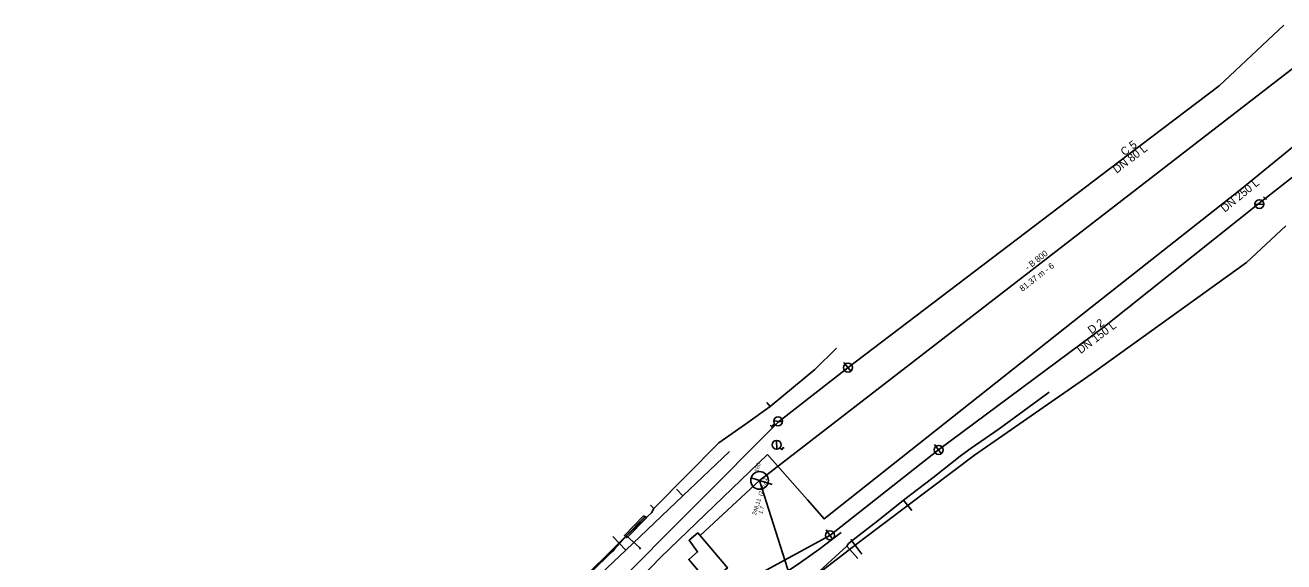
# Model space of a CAD drawing. Extents: x -600636 to -600148, y -1203980 to -1203569.
# Drawn here: x -600456.1 to -600313.9, y -1203630.1 to -1203569.5 of the extents above; entities that cross this region are included whole.
import ezdxf

# ---------------------------------------------------------------- set-up
doc = ezdxf.new("R2010")
doc.units = 0
for name, color, linetype in [('Cetin zam průběh', 7, 'Continuous'), ('EON podzemní NN', 7, 'Continuous'), ('GasNet NTL', 7, 'Continuous'), ('Implicitní', 7, 'Continuous'), ('VaK Břeclav_kanalizace', 7, 'Continuous'), ('Vak Břeclav_vodovod', 7, 'Continuous')]:
    doc.layers.add(name, color=color, linetype=linetype)

# ---------------------------------------------------------------- blocks, each defined once
blk = doc.blocks.new('MoSymbol 2')
at = {"layer": 'Implicitní'}
blk.add_line((0, 0.0005), (0, -0.00075), dxfattribs=at)
blk.add_circle((0, 0), 0.0005, dxfattribs=at)
blk = doc.blocks.new('MoSymbol 3')
at = {"layer": 'Implicitní'}
for p, q in [((-0.000365, -0.000365), (0.000365, 0.000365)), ((-0.000225, 0.00095), (0.000225, 0.00095)), ((0, 0.00095), (0, 0.0005))]:
    blk.add_line(p, q, dxfattribs=at)
blk.add_circle((0, 0), 0.0005, dxfattribs=at)
blk = doc.blocks.new('MoSymbol 4')
at = {"layer": 'Implicitní'}
for p, q in [((-0.000365, -0.000365), (0.000365, 0.000365)), ((0.0003, -0.0008), (0.0002, -0.00085))]:
    blk.add_line(p, q, dxfattribs=at)
blk.add_lwpolyline([(0, -0.0005), (0, -0.0008), (0.0003, -0.0008), (0.0002, -0.00075)], dxfattribs=at)
blk.add_circle((0, 0), 0.0005, dxfattribs=at)

msp = doc.modelspace()

# ---------------------------------------------------------------- linework, layer by layer
at = {"layer": 'Cetin zam průběh'}
for points in [[(-600403.75, -1203662.4), (-600400.59, -1203659.29), (-600391.04, -1203649.83), (-600378.25, -1203637.79), (-600376.97, -1203637.47), (-600375.66, -1203637.95), (-600375.36, -1203637.74), (-600369.01, -1203633.38), (-600361.52, -1203627.61), (-600348.82, -1203618.06), (-600335.53, -1203608.82), (-600318.11, -1203596.27), (-600313.64, -1203592.14)], [(-600371.93, -1203612.56), (-600366.88, -1203608.36), (-600364.43, -1203605.96)], [(-600356.85, -1203623.13), (-600353.54, -1203620.63), (-600350.46, -1203618.17), (-600349.88, -1203617.76), (-600349.23, -1203617.28), (-600346.05, -1203615.09), (-600340.39, -1203610.92)], [(-600385.06, -1203624.09), (-600377.73, -1203616.65), (-600374.7, -1203614.56), (-600371.93, -1203612.56)], [(-600371.93, -1203612.56), (-600372.32, -1203612.09)], [(-600377.73, -1203616.65), (-600374.7, -1203614.56)], [(-600353.54, -1203620.63), (-600350.46, -1203618.17)], [(-600388.16, -1203627.18), (-600385.34, -1203624.55), (-600385.06, -1203624.09)], [(-600385.06, -1203624.09), (-600385.47, -1203623.7)], [(-600359.74, -1203625.45), (-600356.85, -1203623.13)], [(-600356.85, -1203623.13), (-600355.91, -1203624.31)], [(-600388.16, -1203627.18), (-600385.34, -1203624.55)], [(-600363.25, -1203628.32), (-600363.07, -1203628.05), (-600361.87, -1203627.08), (-600359.74, -1203625.45)], [(-600389.61, -1203628.78), (-600389.52, -1203628.69), (-600388.16, -1203627.18)], [(-600389.52, -1203628.69), (-600388.16, -1203627.18)], [(-600388.16, -1203627.18), (-600386.71, -1203628.5)], [(-600388.16, -1203627.18), (-600386.71, -1203628.5), (-600386.58, -1203628.67)], [(-600368.09, -1203632.74), (-600363.25, -1203628.32)], [(-600363.25, -1203628.32), (-600362.03, -1203629.72)], [(-600363.07, -1203628.05), (-600361.87, -1203627.08)], [(-600396.73, -1203635.32), (-600394.24, -1203633.29), (-600389.88, -1203629.05)], [(-600389.88, -1203629.05), (-600389.61, -1203628.78)]]:
    msp.add_lwpolyline(points, dxfattribs=at)
at = {"layer": 'EON podzemní NN'}
msp.add_lwpolyline([(-600394.24, -1203633.14), (-600388.26, -1203627.25), (-600386.06, -1203624.99)], dxfattribs=at)
msp.add_lwpolyline([(-600386.23, -1203624.89), (-600385.88, -1203625.09), (-600388.12, -1203627.38), (-600388.4, -1203627.11)], close=True, dxfattribs=at)
at = {"layer": 'GasNet NTL'}
for points in [[(-600376.52, -1203617.62), (-600381.81, -1203622.65), (-600388.25, -1203628.77), (-600399.65, -1203639.6), (-600410.04, -1203649.48), (-600410.35, -1203649.77), (-600417.47, -1203657.21), (-600420.27, -1203660.14), (-600432.74, -1203673.17), (-600439.94, -1203680.7), (-600445.87, -1203686.85), (-600458.57, -1203700.01), (-600466.75, -1203707.26), (-600469.55, -1203709.74), (-600472.59, -1203712.26), (-600475.67, -1203714.29), (-600481.14, -1203718.36), (-600486.68, -1203722.48)], [(-600382.53, -1203621.89), (-600381.81, -1203622.65)], [(-600363.91, -1203626.79), (-600366.43, -1203628.72), (-600368.49, -1203630.18), (-600377.69, -1203636.35), (-600377.83, -1203636.45), (-600379.12, -1203637.4), (-600390.52, -1203649.08), (-600393.75, -1203652.39), (-600407.12, -1203666.06), (-600410.69, -1203669.71), (-600416.55, -1203675.06), (-600425.93, -1203683.63), (-600443.22, -1203700.03), (-600443.4, -1203700.21), (-600447.92, -1203704.5), (-600448.05, -1203704.62)], [(-600389.69, -1203627.25), (-600388.25, -1203628.77)], [(-600362.82, -1203627.58), (-600361.57, -1203629.22)]]:
    msp.add_lwpolyline(points, dxfattribs=at)
at = {"layer": 'VaK Břeclav_kanalizace'}
for p, q in [((-600309.64, -1203571.84), (-600373.13, -1203620.91)), ((-600373.13, -1203620.91), (-600379.85, -1203627.13)), ((-600373.13, -1203620.91), (-600367.91, -1203637.36))]:
    msp.add_line(p, q, dxfattribs=at)
msp.add_lwpolyline([(-600380.11, -1203626.82), (-600381.1, -1203627.66), (-600380.13, -1203628.99), (-600381.12, -1203629.83), (-600378.83, -1203632.54), (-600376.75, -1203630.79)], close=True, dxfattribs=at)
at = {"layer": 'Vak Břeclav_vodovod'}
for p, q in [((-600316.71, -1203589.64), (-600300.57, -1203576.9)), ((-600363.13, -1203608.16), (-600370.99, -1203614.29)), ((-600370.99, -1203614.29), (-600423.62, -1203667.02)), ((-600365.17, -1203627.11), (-600352.89, -1203617.46)), ((-600377.98, -1203634.08), (-600365.17, -1203627.11))]:
    msp.add_line(p, q, dxfattribs=at)
for points in [[(-600313.89, -1203569.48), (-600321.18, -1203576.33), (-600332.51, -1203584.93), (-600363.13, -1203608.16)], [(-600303.26, -1203575.4), (-600318.68, -1203587.96), (-600335.72, -1203601.41), (-600365.84, -1203625.25), (-600367.7, -1203623.11), (-600372.22, -1203617.99)], [(-600352.89, -1203617.46), (-600334.15, -1203603.51), (-600316.71, -1203589.64)], [(-600372.22, -1203617.99), (-600384.28, -1203629.56), (-600410.01, -1203656.15), (-600451.09, -1203698.02), (-600454.25, -1203701.01)]]:
    msp.add_lwpolyline(points, dxfattribs=at)

# ---------------------------------------------------------------- block references
at = {"layer": 'VaK Břeclav_kanalizace', "xscale": 1999.7500312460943, "yscale": 1999.750031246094, "rotation": 72.64048260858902}
msp.add_blockref('MoSymbol 2', (-600373.13, -1203620.91), dxfattribs=at)
at = {"layer": 'Vak Břeclav_vodovod'}
for name, p, xscale, yscale, rotation in [('MoSymbol 3', (-600316.65, -1203589.7), 999.875015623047, 999.8750156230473, -42.80392229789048), ('MoSymbol 2', (-600363.13, -1203608.16), 999.875015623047, 999.875015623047, -142.43906434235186), ('MoSymbol 3', (-600371.03, -1203614.23), 999.8750156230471, 999.8750156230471, 128.5630116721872), ('MoSymbol 4', (-600371.2, -1203616.88), 999.8750156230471, 999.8750156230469, 47.66988975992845), ('MoSymbol 2', (-600352.89, -1203617.46), 999.8750156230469, 999.8750156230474, -142.5887421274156), ('MoSymbol 2', (-600365.17, -1203627.11), 999.8750156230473, 999.875015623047, -146.63737693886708)]:
    msp.add_blockref(name, p, dxfattribs=dict(at, xscale=xscale, yscale=yscale, rotation=rotation))

# ---------------------------------------------------------------- texts
at = {"layer": 'VaK Břeclav_kanalizace'}
for s, height, rotation, p in [('- B 800', 0.682, 37.6984, (-600342.81, -1203597.19)), ('81.37 m - 6', 0.6824, 37.6984, (-600343.42, -1203599.61)), ('160', 0.455, 72.6405, (-600373.31, -1203619.99)), ('248,11  (246,41)', 0.4549, 72.6405, (-600373.54, -1203624.85)), ('1.7', 0.455, 72.6405, (-600372.84, -1203624.73))]:
    msp.add_text(s, height=height, rotation=rotation, dxfattribs=at).set_placement(p)
at = {"layer": 'Vak Břeclav_vodovod'}
for s, rotation, p in [('C 5', 37.1988, (-600331.9, -1203584.29)), ('DN 80 L', 37.1988, (-600332.77, -1203586.27)), ('DN 250 L', 39.1629, (-600320.55, -1203590.67)), ('D 2', 36.656, (-600335.61, -1203604.42)), ('DN 150 L', 36.656, (-600336.84, -1203606.64))]:
    msp.add_text(s, height=0.91, rotation=rotation, dxfattribs=at).set_placement(p)

doc.saveas('drawing.dxf')
